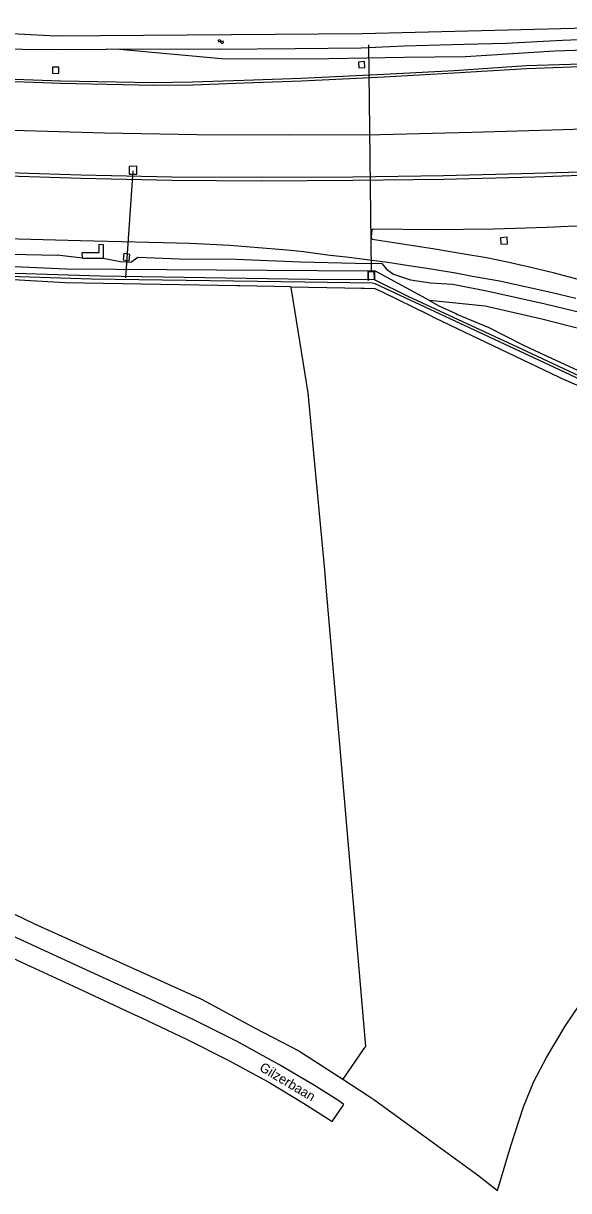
# Model space of a CAD drawing. Extents: x 126000 to 131009, y 393000 to 395500.
# Drawn here: x 128053 to 128195.5, y 394161.7 to 394466.8 of the extents above; entities that cross this region are included whole.
import ezdxf

# ---------------------------------------------------------------- set-up
doc = ezdxf.new("R2010")
doc.units = 0
for name, color, linetype in [('gg-anno-openbare ruimte label', 7, 'Continuous'), ('gg-knt-BGT kruinlijn', 7, 'Continuous'), ('gg-kntw-bovenkant insteek waterloop', 7, 'Continuous'), ('gg-kwrk-duiker nz buis', 7, 'Continuous'), ('gg-kwrk-uitstroombak niveau min 01', 7, 'Continuous'), ('gt-symb-watersymbool', 7, 'Continuous'), ('gx-grn-maaiveld', 7, 'Continuous')]:
    doc.layers.add(name, color=color, linetype=linetype)

# ---------------------------------------------------------------- blocks, each defined once
blk = doc.blocks.new('gt0-WA')
at = {"layer": 'gt-symb-watersymbool'}
for centre, start, end in [((-0.32, 0.02), 28.0725, 151.9275), ((0.43, 0.42), 208.0725, 331.9275), ((-0.32, -0.43), 28.0725, 151.9275), ((0.43, -0.03), 208.0725, 331.9275)]:
    blk.add_arc(centre, 0.425, start, end, dxfattribs=at)

msp = doc.modelspace()

# ---------------------------------------------------------------- linework, layer by layer
at = {"layer": 'gg-knt-BGT kruinlijn'}
for p, q in [((128105.78, 394457.43), (128078.11, 394460)), ((128220.46, 394460.5), (128191.97, 394459.5)), ((128132.86, 394457.5), (128105.78, 394457.43)), ((128142.68, 394457.7), (128132.86, 394457.5)), ((128152.59, 394457.83), (128142.68, 394457.7)), ((128168.54, 394458.02), (128152.59, 394457.83)), ((128191.97, 394459.5), (128168.54, 394458.02)), ((128049.61, 394406.42), (128061.86, 394406.24)), ((128068.48, 394405.41), (128061.86, 394406.24)), ((128068.48, 394405.41), (128073.83, 394405.42)), ((128073.83, 394405.42), (128078.36, 394404.57)), ((128081.09, 394404.41), (128082.91, 394405.65)), ((128082.91, 394405.65), (128093.7, 394405.27)), ((128093.7, 394405.27), (128108.67, 394405.16)), ((128108.67, 394405.16), (128125.44, 394404.44)), ((128078.36, 394404.57), (128081.09, 394404.41)), ((128125.44, 394404.44), (128139.82, 394404.13)), ((128139.82, 394404.13), (128146.67, 394404)), ((128146.67, 394404), (128147.93, 394402.5)), ((128147.93, 394402.5), (128149.79, 394401.22)), ((128149.79, 394401.22), (128154.23, 394399.74)), ((128154.23, 394399.74), (128159.45, 394399)), ((128159.45, 394399), (128165.26, 394398.59)), ((128165.26, 394398.59), (128174.97, 394396.74)), ((128174.97, 394396.74), (128189.4, 394393.44)), ((128189.4, 394393.44), (128203.01, 394390.21))]:
    msp.add_line(p, q, dxfattribs=at)
at = {"layer": 'gg-kntw-bovenkant insteek waterloop'}
msp.add_line((128160.58, 394389.86), (128194.92, 394373.44), dxfattribs=at)
msp.add_lwpolyline([(128246.39, 394466.8), (128225.81, 394465.91), (128210.82, 394465.8), (128141.59, 394464.07), (128061.61, 394463.44), (128000, 394466.69)], dxfattribs=at)
at = {"layer": 'gg-kwrk-duiker nz buis'}
for p, q in [((128143.25, 394461.15), (128143.9, 394402.14)), ((128081.62, 394428.25), (128079.69, 394400.26))]:
    msp.add_line(p, q, dxfattribs=at)
at = {"layer": 'gg-kwrk-uitstroombak niveau min 01'}
msp.add_line((128143.03, 394402.14), (128144.85, 394402.13), dxfattribs=at)
msp.add_lwpolyline([(128143.03, 394402.14), (128143.02, 394399.7), (128143.22, 394399.69), (128143.23, 394401.94), (128144.65, 394401.93), (128144.67, 394399.87), (128144.87, 394399.87), (128144.85, 394402.13)], dxfattribs=at)
at = {"layer": 'gx-grn-maaiveld'}
for p, q in [((128078.11, 394460), (128074.66, 394460.01)), ((128104.2, 394460.05), (128078.11, 394460)), ((128159.13, 394394.31), (128144.85, 394402.13)), ((128159.13, 394394.31), (128161.44, 394393.05)), ((128161.44, 394393.05), (128166.03, 394390.91)), ((128186.73, 394381.28), (128235.73, 394358.49))]:
    msp.add_line(p, q, dxfattribs=at)
for points in [[(128388.04, 394466.44), (128355, 394464.23), (128323.99, 394462.35), (128296.88, 394460.75), (128270.48, 394459.29), (128244.6, 394457.87), (128219.15, 394456.69), (128196.04, 394456.06), (128184.45, 394455.66), (128165.58, 394454.41), (128147.25, 394453.41), (128125.65, 394452.38), (128110.6, 394451.85), (128097.21, 394451.43), (128086.94, 394451.23), (128062.72, 394451.7), (128034.08, 394452.73)], [(128104.2, 394460.05), (128124.09, 394460.25), (128141.28, 394460.42), (128152.52, 394460.91), (128168.24, 394461.35), (128179.15, 394461.58), (128193.96, 394462.41), (128211.07, 394463.08), (128220.64, 394463.54), (128235.61, 394464.18), (128256.36, 394464.99), (128268.2, 394465.68), (128279.54, 394466.13), (128292.05, 394466.4)], [(128388.12, 394465.71), (128355.03, 394463.55), (128324.01, 394461.62), (128296.82, 394460.03), (128270.53, 394458.64), (128244.66, 394457.33), (128219.14, 394456.1), (128196.08, 394455.31), (128184.5, 394454.87), (128165.65, 394453.76), (128147.28, 394452.75), (128125.71, 394451.65), (128110.71, 394451.12), (128097.31, 394450.67), (128087.01, 394450.56), (128062.72, 394451.06), (128034.24, 394452.12)], [(128031.94, 394460.87), (128052.8, 394460.09), (128061.68, 394459.99), (128074.66, 394460.01)], [(128140.63, 394456.69), (128140.73, 394455.18), (128142.3, 394455.27), (128142.2, 394456.79), (128140.63, 394456.69)], [(128060.67, 394455.38), (128060.62, 394453.74), (128062.24, 394453.71), (128062.32, 394455.32), (128060.67, 394455.38)], [(128389.91, 394449.52), (128361.4, 394447.67), (128337.4, 394446.25), (128313.8, 394444.8), (128289.52, 394443.39), (128265.75, 394442.05), (128241.98, 394440.72), (128217.94, 394439.71), (128194.07, 394438.92), (128170.2, 394438.24), (128146.28, 394437.68), (128122.21, 394437.57), (128098.33, 394437.65), (128074.26, 394438.08), (128050.32, 394438.82), (128037.58, 394439.43)], [(128236.97, 394428.62), (128236.88, 394429.42), (128210.42, 394428.23), (128186.63, 394427.54), (128162.86, 394426.92), (128139.13, 394426.55), (128115.19, 394426.47), (128091.82, 394426.61), (128068.15, 394427.1), (128040.59, 394427.98)], [(128080.68, 394429.41), (128080.7, 394427.35), (128082.69, 394427.37), (128082.68, 394429.43), (128080.68, 394429.41)], [(128621.7, 394427.7), (128578.07, 394424.73), (128574.89, 394424.11), (128554.72, 394417.55), (128529.2, 394408.83), (128494.65, 394396.63), (128449.44, 394381.11), (128416.1, 394369.29), (128388.22, 394360.67), (128386.42, 394360.54), (128356.09, 394358.68), (128296.59, 394354.79), (128248.05, 394351.67), (128246.26, 394351.77), (128234.12, 394356.98), (128193.15, 394376.25), (128145, 394398.73), (128144.2, 394398.88), (128126.57, 394399.13), (128070.86, 394399.9), (128038.39, 394400.99)], [(128040.79, 394427.2), (128068.1, 394426.33), (128091.73, 394425.78), (128115.27, 394425.63), (128139.15, 394425.77), (128162.87, 394426.09), (128186.7, 394426.68), (128210.36, 394427.51), (128236.97, 394428.62)], [(128198.35, 394399.75), (128191.81, 394401.48), (128185.31, 394403.07), (128179.09, 394404.49), (128174.03, 394405.49), (128167.74, 394406.58), (128160.57, 394407.75), (128154.34, 394408.73), (128144.19, 394410.26), (128143.99, 394410.8), (128144.22, 394412.91), (128144.57, 394413.08), (128159.95, 394412.91), (128176.11, 394413.07), (128189.73, 394413.5), (128195.4, 394413.79), (128210.98, 394414.3)], [(128177.76, 394410.73), (128177.79, 394409.1), (128179.54, 394409.16), (128179.51, 394410.88), (128177.76, 394410.73)], [(128045.14, 394410.64), (128067.97, 394410.04), (128096.59, 394409.31), (128106.95, 394408.82), (128119.76, 394407.74), (128122.89, 394407.48), (128126.22, 394407.12), (128133.24, 394406.24), (128137.38, 394405.74), (128142.21, 394405.13), (128148.3, 394404.36), (128153.81, 394403.47), (128159.63, 394402.63), (128166, 394401.62), (128170.41, 394400.74), (128177.43, 394399.49), (128184.19, 394398.05), (128190.89, 394396.54), (128197.46, 394394.99)], [(128068.48, 394405.41), (128068.42, 394406.89), (128072.8, 394406.9), (128072.8, 394409.1), (128073.85, 394409.03), (128073.83, 394405.42)], [(128080.65, 394404.75), (128080.86, 394406.4), (128079.28, 394406.6), (128079.07, 394404.95), (128080.65, 394404.75)], [(128122.88, 394397.92), (128109.71, 394398.15), (128109.46, 394398.15), (128108.85, 394398.16), (128063.97, 394398.95), (128053.43, 394399.57), (128053.39, 394399.57), (128000, 394402.7)], [(128039.67, 394401.85), (128073.08, 394400.81), (128133.23, 394399.88), (128142.8, 394399.92), (128144.7, 394399.86), (128153.48, 394395.47), (128183.21, 394381.74), (128209.25, 394369.54), (128224.5, 394362.5), (128236.16, 394357.07), (128245.4, 394352.83), (128246.42, 394352.46), (128247.83, 394352.36), (128248.42, 394352.35), (128249.02, 394352.43), (128296.4, 394355.78), (128346.08, 394358.89), (128386.31, 394361.29), (128389.89, 394361.92), (128414.49, 394369.52)], [(128047.05, 394403.38), (128064.15, 394402.64), (128143.03, 394402.14)], [(128122.88, 394397.92), (128137.04, 394397.67), (128141.4, 394397.59), (128141.81, 394397.59), (128142.12, 394397.58), (128144.89, 394397.53), (128146.81, 394396.59), (128158.89, 394390.69), (128159.07, 394390.6), (128160.58, 394389.86)], [(128122.88, 394397.92), (128122.99, 394397.23), (128127.37, 394370.19), (128131.69, 394323.85), (128132.11, 394319.4), (128135.71, 394277.33), (128142.4, 394199.38), (128142.04, 394198.84), (128136.55, 394190.77)], [(128277.42, 394371.77), (128272.56, 394370.58), (128268.09, 394370.4), (128262.48, 394371.82), (128251.12, 394374.73), (128235.71, 394378.24), (128220.71, 394381.66), (128203.53, 394385.65), (128188.5, 394389.46), (128173.69, 394392.88), (128159.13, 394394.31)], [(128166.03, 394390.91), (128166.49, 394390.71), (128174.67, 394387.28), (128183.55, 394382.8), (128186.73, 394381.28)], [(128251.14, 394350.96), (128251, 394350.97), (128250.72, 394350.97), (128250.66, 394350.97), (128246.03, 394351.06), (128243.49, 394351.27), (128241.43, 394352.12), (128236.15, 394354.54), (128235.7, 394354.75), (128235.66, 394354.77), (128221.01, 394361.48), (128220.86, 394361.55), (128206.25, 394368.25), (128206.07, 394368.33), (128199.87, 394371.17), (128199.38, 394371.4), (128199.21, 394371.48), (128194.92, 394373.44)], [(128018.49, 394248.57), (128028.28, 394244.76), (128055.92, 394231.42), (128099.57, 394211.73), (128113.61, 394204.11), (128125.05, 394198.2), (128136.55, 394190.77)], [(128136.55, 394190.77), (128143.06, 394186.5), (128144.87, 394185.31), (128171.69, 394165.8), (128176.98, 394161.66), (128180.46, 394173.38), (128183.75, 394183.59), (128186.44, 394190.15), (128189.73, 394196.5), (128194.6, 394204.64), (128208.62, 394225.39), (128210.95, 394228.83), (128218.49, 394237.49), (128222.62, 394240.58), (128226.27, 394242.72), (128228.89, 394243.36), (128231.89, 394241.56), (128253.11, 394227.04), (128252.71, 394238.97), (128252.47, 394247.5), (128252.79, 394248.93)], [(128041.14, 394226.63), (128066.08, 394215.1), (128082.17, 394207.66), (128083.52, 394207.03), (128087.16, 394205.3), (128095.64, 394201.29), (128106.37, 394195.87), (128117.14, 394190), (128126.22, 394184.52), (128132.95, 394180.26), (128133.76, 394179.73), (128136.81, 394184.22), (128135.19, 394185.29), (128129.09, 394189.11), (128119.78, 394194.62), (128108.89, 394200.62), (128097.94, 394206.17), (128086.13, 394211.75), (128068.43, 394219.85), (128043.19, 394231.39)]]:
    msp.add_lwpolyline(points, dxfattribs=at)

# ---------------------------------------------------------------- block references
at = {"layer": 'gt-symb-watersymbool', "rotation": 3.726425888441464}
msp.add_blockref('gt0-WA', (128104.57, 394462.04), dxfattribs=at)

# ---------------------------------------------------------------- texts
at = {"layer": 'gg-anno-openbare ruimte label'}
msp.add_text('Gilzerbaan', height=2.5, rotation=329.2, dxfattribs=at).set_placement((128114.49, 394193.19))

doc.saveas('drawing.dxf')
